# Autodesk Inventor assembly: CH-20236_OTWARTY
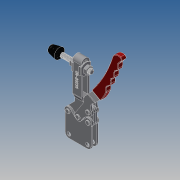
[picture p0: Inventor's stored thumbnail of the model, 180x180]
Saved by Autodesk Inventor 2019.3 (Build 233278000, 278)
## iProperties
Company: ·L?¤¤?
Created: 2010-06
Part Number: CH-20236_OTWARTY
Material: Ogólny
Description: STEP AP203
Document SubType Name: Assembly
Designer: CADENGINEERING4
Sending System: SolidWorks 2005179
Preprocessor: SwSTEP 2.0
Title: CH-20236.STEP
Author: ·L?¥Î?
Revision Number: ANY
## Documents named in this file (9)
- E:\STRONA\Horizontal toggle clamp\CH-20236\CH-20236_OTWARTY.iam
- E:\STRONA\Horizontal toggle clamp\CH-20236\20235-03___.ipt
- E:\STRONA\Horizontal toggle clamp\CH-20236\38312-02___.ipt
- E:\STRONA\Horizontal toggle clamp\CH-20236\FW380___.ipt
- E:\STRONA\Horizontal toggle clamp\CH-20236\20235-04___.ipt
- E:\STRONA\Horizontal toggle clamp\CH-20236\20235-05___.ipt
- E:\STRONA\Horizontal toggle clamp\CH-20236\20236-01___.ipt
- E:\STRONA\Horizontal toggle clamp\CH-20236\20236-02___.ipt
- E:\STRONA\Horizontal toggle clamp\CH-20236\CH-FC-38312___.ipt
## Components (14 placed, 14 different names)
1. 20235-03_??_1 — Zestawiające:14, Zestawiające:16, Zestawiające:18, Zestawiające:19, Zestawiające:25, Zestawiające:26, Zestawiające:27, Przejściowe:1
2. 38312-02_??_2 — Równoległe:1, Zestawiające:1, Zestawiające:3
3. FW380_??_3 — Równoległe:3, Zestawiające:5, Zestawiające:6, Zestawiające:8
4. 20235-04_??_4 — Zestawiające:10, Zestawiające:11, Zestawiające:12
5. 38312-02_??_5 — Zestawiające:6, Zestawiające:7
6. FW380_??_6 — Równoległe:2, Równoległe:3, Zestawiające:2, Zestawiające:3, Zestawiające:4
7. 20235-05_??_7 — Zestawiające:23, Zestawiające:24
8. 20235-05_??_8 — Zestawiające:18, Zestawiające:19
9. 20236-01_??_9 — Zestawiające:13, Zestawiające:15, Zestawiające:17, Zestawiające:20, Zestawiające:21, Zestawiające:22, Zestawiające:23, Zestawiające:24, Przejściowe:1
10. 20236-02_??_10 — Równoległe:2, Zestawiające:4, Zestawiające:8, Zestawiające:9, Zestawiające:21, Zestawiające:22, Zestawiające:25
11. 20235-05_??_11 — Zestawiające:26, Zestawiające:27
12. 20235-04_??_12 — Zestawiające:10, Zestawiające:11, Zestawiające:12, Zestawiające:13, Zestawiające:14, Zestawiające:15, Zestawiające:16
13. CH-FC-38312_??_13 — Równoległe:1, Zestawiające:1, Zestawiające:2, Zestawiające:5, Zestawiające:7, Zestawiające:9
14. 20235-05_??_14 — Zestawiające:17, Zestawiające:20
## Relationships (31: Mate 27, Flush 3, Transitional 1)
- Równoległe:1 [Flush]: 38312-02_??_2 ↔ CH-FC-38312_??_13
- Równoległe:2 [Flush]: FW380_??_6 ↔ 20236-02_??_10
- Równoległe:3 [Flush]: FW380_??_3 ↔ FW380_??_6
- Zestawiające:1 [Mate]: 38312-02_??_2 ↔ CH-FC-38312_??_13
- Zestawiające:2 [Mate]: FW380_??_6 ↔ CH-FC-38312_??_13
- Zestawiające:3 [Mate]: 38312-02_??_2 ↔ FW380_??_6
- Zestawiające:4 [Mate]: FW380_??_6 ↔ 20236-02_??_10
- Zestawiające:5 [Mate]: FW380_??_3 ↔ CH-FC-38312_??_13
- Zestawiające:6 [Mate]: FW380_??_3 ↔ 38312-02_??_5
- Zestawiające:7 [Mate]: 38312-02_??_5 ↔ CH-FC-38312_??_13
- Zestawiające:8 [Mate]: FW380_??_3 ↔ 20236-02_??_10
- Zestawiające:9 [Mate]: 20236-02_??_10 ↔ CH-FC-38312_??_13
- Zestawiające:10 [Mate]: 20235-04_??_4 ↔ 20235-04_??_12
- Zestawiające:11 [Mate]: 20235-04_??_4 ↔ 20235-04_??_12
- Zestawiające:12 [Mate]: 20235-04_??_4 ↔ 20235-04_??_12
- Zestawiające:13 [Mate]: 20236-01_??_9 ↔ 20235-04_??_12
- Zestawiające:14 [Mate]: 20235-03_??_1 ↔ 20235-04_??_12
- Zestawiające:15 [Mate]: 20236-01_??_9 ↔ 20235-04_??_12
- Zestawiające:16 [Mate]: 20235-03_??_1 ↔ 20235-04_??_12
- Zestawiające:17 [Mate]: 20236-01_??_9 ↔ 20235-05_??_14
- Zestawiające:18 [Mate]: 20235-03_??_1 ↔ 20235-05_??_8
- Zestawiające:19 [Mate]: 20235-03_??_1 ↔ 20235-05_??_8
- Zestawiające:20 [Mate]: 20236-01_??_9 ↔ 20235-05_??_14
- Zestawiające:21 [Mate]: 20236-01_??_9 ↔ 20236-02_??_10
- Zestawiające:22 [Mate]: 20236-01_??_9 ↔ 20236-02_??_10
- Zestawiające:23 [Mate]: 20235-05_??_7 ↔ 20236-01_??_9
- Zestawiające:24 [Mate]: 20235-05_??_7 ↔ 20236-01_??_9
- Zestawiające:25 [Mate]: 20235-03_??_1 ↔ 20236-02_??_10
- Zestawiające:26 [Mate]: 20235-03_??_1 ↔ 20235-05_??_11
- Zestawiające:27 [Mate]: 20235-03_??_1 ↔ 20235-05_??_11
- Przejściowe:1 [Transitional]: 20235-03_??_1 ↔ 20236-01_??_9
